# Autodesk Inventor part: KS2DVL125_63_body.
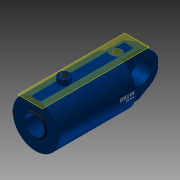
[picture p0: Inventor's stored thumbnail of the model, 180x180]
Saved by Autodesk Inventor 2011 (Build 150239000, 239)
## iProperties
Created: 2010-11
Document SubType Name: Modeling
Designer: TB
Mass: 405.061 g
Surface Area: 916.939 cm^2
Volume: 405.061 cm^3
Density: 1 g/cm^3
Author: TB
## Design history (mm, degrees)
sketch "Sketch2"
  geometry: L1 (-35, -3)-(-35, 3); L2 (-35, -9)-(-35, 9); L3 (-35, 0)-(-35, 72.5); L4 (-35, 72.5)-(-300, 72.5); L5 (-300, 72.5)-(-300, 72.5); L6 (-300, 72.5)-(-310, 72.5); L7 (-310, 72.5)-(-310, 35.5); L8 (-310, 35.5)-(-313, 32.5); L9 (-313, 32.5)-(-313, 31.5); L10 (-313, 31.5)-(-218, 31.5); L11 (-218, 31.5)-(-218, 62.5); L12 (-218, 62.5)-(-66, 62.5); L13 (-66, 62.5)-(-66, 0); L14 (-66, 0)-(-35, 0); L15 (-66, 0)-(-148.421, 0); L16 (-35, 9)-(-32, 12) reference; L17 (-32, 12)-(-35, 12) reference; L18 (-35, 12)-(-35, 9) reference; L19 (-32, 12)-(-35, 9) reference; L20 (-32, 12)-(-35, 12) reference; L21 (-35, 9)-(-35, 12) reference; L22 (-35, 9)-(-32, 12) reference; 1 further point
  constraints: 44 end point, 8 perpendicular, 6 parallel, 5 collinear, 2 horizontal, 2 vertical, 1 coincident, 1 midpoint, 1 point on line, 10 other
  dimensions: "DiaY" = 145 diameter of L4 L15; "DiaI" = 125 diameter of L12 L15; "d4" = 1 distance of L8.end L9.end; "d5" = 45 deg angle of L10 L8; "d6" = 3 distance between parallel lines of L7 L9; "DiaStang" = 63 diameter of L10 L15; "RindDia" = 145 diameter of L6 L15; "RingLengde" = 10 distance of L5.end L6.end; "RingTykk" = 92 distance between parallel lines of L11 L7; "KroppLengde" = 275 distance between parallel lines of L7 L3 (derived); "BunnTykkelse" = 31 distance between parallel lines of L13 L3
revolve "Kropp" sketch "Sketch2" stored, may be unused: angle "d13" = 90 deg
sketch "Sketch3"
  geometry: L1 (-66, -62.5)-(-66, 62.5) reference; L2 (-66, 0.01)-(-166, 0.01); L3 (-166, -0.01)-(-66, -0.01); A1 r 0.01 centre (-166, 0) between (-166, 0.01) and (-166, -0.01); A2 r 0.01 centre (-66, 0) between (-66, -0.01) and (-66, 0.01); 2 further points
  constraints: 4 end point, 4 point on circle, 4 tangent, 2 centre point, 1 coincident, 1 midpoint, 1 parallel, 1 perpendicular
  dimensions: "d17" = 0.01 radius of A2; "d18" = 100 distance of L2.start L2.end (= Slaglengde)
feature "BaneTransitionalConstraint" sketch "Sketch3" dims "d19" = 2, "d20" = 0
sketch "Sketch6"
  geometry: L1 (-101.5, 0)-(101.5, 0) reference; L2 (14.671, 71)-(-11.843, 71); L3 (72.5, 0)-(72.5, 31.248); L4 (-72.5, 0)-(-72.5, -18.451); A1 r 72.5 centre (0, 0) between (-72.5, 0) and (72.5, 0) reference; 2 further points
  constraints: 6 end point, 2 point on circle, 2 vertical, 2 other
  dimensions: "d30" = 71 distance from line of point (0, 0) L2 (computed from DiaY); "d31" = 0 deg angle of L1 L2 (computed from Vinkel_Plussport); "d37" = 90 deg angle of L2 L3; "d38" = 90 deg angle of L2 L4
  node "Projected Loop3"
workplane "Work Plane5"
sketch "Sketch7"
  geometry: L1 (14.671, -375.6)-(14.671, 62.6) reference; L2 (-19.633, -35)-(38.367, -35) reference; C1 r 17.5 at (14.671, -52.5); 1 further point
  constraints: 1 centre point, 1 point on line
  dimensions: "PortDia" = 35 diameter of C1
extrude "Extrusion2" cut sketch "Sketch7" stored distance "d34" = 1.5; taper "d35" = 0 deg
workplane "Work Plane7"
sketch "Sketch4"
  geometry: L1 (-16.68, -40)-(-16.68, -78.777); L2 (-16.68, -78.777)-(16.68, -78.777); L3 (16.68, -78.777)-(16.68, -40); L4 (16.68, -40)-(-16.68, -40); L5 (-40.643, -40)-(0, -40); L6 (-29, -35)-(29, -35); L7 (0, -35)-(0, -40); 2 further points
  constraints: 6 end point, 2 midpoint, 2 other
  dimensions: "d40" = 5 distance of L7.start L5.end
emboss "Emboss1" sketch "Sketch4" dims "d4" = 1, "d5" = 45 deg, "d6" = 3, "d22" = 0.2, "d23" = 0, "DiaI" = 125, "DiaY" = 145, "RindDia" = 145, "DiaStang" = 63, "RingTykk" = 92, "RingLengde" = 10, "KroppLengde" = 275 (derived), "BunnTykkelse" = 31
workplane "Work Plane8"
sketch "Sketch8"
  geometry: L1 (-29, -35)-(29, -35); L2 (0, -35)-(0, -40); L3 (-5.906, -110.587)-(-5.906, -40); L4 (-5.906, -40)-(5.906, -40); L5 (5.906, -40)-(5.906, -110.587); L6 (5.906, -110.587)-(-5.906, -110.587); L7 (72.5, -35)-(-72.5, -35); L8 (72.5, -35)-(-72.5, -35) reference; 3 further points
  constraints: 6 end point, 4 midpoint, 2 other
  dimensions: "d42" = 5 distance of L2.start L2.end
emboss "Emboss2" sketch "Sketch8" dims "d4" = 1, "d5" = 45 deg, "d6" = 3, "d43" = 0.2, "d44" = 0, "DiaI" = 125, "DiaY" = 145, "RindDia" = 145, "DiaStang" = 63, "RingTykk" = 92, "RingLengde" = 10, "KroppLengde" = 275 (derived), "BunnTykkelse" = 31
sketch "Sketch9"
  geometry: A1 r 12.5 centre (9.367, -52.5) between (0, -60.776) and (18.735, -60.776) reference; 1 further point
hole "Hole1" sketch "Sketch9" at (9.367, -52.5) diameter "d45" = 14.95; stored, may be unused: countersink angle "d49" = 82 deg, drill point angle "d51" = 118 deg; dims "d46" = 6, "d47" = 3.023, "d48" = 2, "DiaInvPluss" = 24.5
workplane "Work Plane9"
sketch "Sketch10"
  geometry: L1 (-101.5, 0)-(101.5, 0) reference; L2 (0, 72.5)-(13.136, 72.5); L3 (0, 72.5)-(0, 31.79); L4 (17.5, 70.356)-(17.5, 90); L5 (17.5, 90)-(0, 90); L6 (0, 90)-(0, 72.5); L7 (0, 72.5)-(17.5, 70.356); C1 r 72.5 at (0, 0) reference; A1 r 72.5 centre (0, 0) between (0, 72.5) and (17.5, 70.356); 1 further point
  constraints: 12 end point, 4 perpendicular, 2 concentric, 2 point on circle, 1 centre point, 1 point on line, 1 tangent
  dimensions: "d53" = 0 deg angle of L1 L2 (computed from Vinkel_Minusport); "DiaUtvStussMinus" = 35 diameter of L4 L3; "HøydeStussMinuss" = 17.5 distance between parallel lines of L2 L5
revolve "Revolution2" sketch "Sketch10" stored, may be unused: angle "d56" = 90 deg
hole "Hole2" diameter "d59" = 24.117; stored, may be unused: countersink angle "d63" = 82 deg, drill point angle "d65" = 118 deg; dims "d57" = 10, "d58" = 10, "d60" = 6, "d61" = 3.023, "d62" = 2, "DiaInvStussMinus" = 24.5
fillet "Fillet1" dims "d66" = 2
sketch "Sketch15"
  geometry: L1 (25, -68.053)-(25, 68.053); L2 (-25, -68.053)-(-25, 68.053); L3 (0, 101.5)-(0, -101.5) reference; A1 r 72.5 centre (0, 0) between (25, -68.053) and (-25, -68.053) reference; A2 r 72.5 centre (0, 0) between (25, 68.053) and (-25, 68.053); A3 r 72.5 centre (0, 0) between (-25, -68.053) and (25, -68.053)
  constraints: 8 point on circle, 4 end point, 4 point on line, 2 centre point, 2 concentric, 2 parallel, 1 coincident
  dimensions: "EyeBunnTykk" = 25 distance from line of L1 A1.centre; "EyeBunnTykk2" = 25 distance from line of A1.centre L2
extrude "Extrusion6" join sketch "Sketch15" taper "d98" = 0 deg; distance "LengdeEyeMinussBunntykk" = 136
sketch "Sketch16"
  geometry: L1 (-309, 72.5)-(101, 72.5) reference; L2 (-309, -72.5)-(101, -72.5) reference; L3 (-309, 72.5)-(101, 72.5) reference; L4 (101, 72.5)-(101, 68.053) reference; L5 (101, -68.053)-(101, 68.053) reference; L6 (-355.272, 0)-(192.63, 0) reference; L7 (36.5, 72.5)-(101, 72.5); L8 (101, 72.5)-(101, 8); A1 r 64.5 centre (36.5, 8) between (101, 8) and (36.5, 72.5); 6 further points; 2 other entities
  constraints: 4 end point, 4 tangent, 2 point on circle, 2 point on line, 1 centre point, 1 collinear, 1 perpendicular, 2 other
  dimensions: "d137" = 8 distance from line of L8.end L6
extrude "Extrusion7" cut sketch "Sketch16" taper "d102" = 0 deg; stored distance "ExtruEyeBunn" = 50
mirror "Mirror1"
sketch "Sketch20"
  geometry: L1 (-309, 72.5)-(101, 72.5) reference; L2 (101, -68.053)-(101, 68.053) reference; L3 (101, 72.5)-(101, 68.053) reference; L4 (-353.49, 0)-(181.938, 0) reference; L5 (-35, -68.053)-(-35, 68.053) reference; L6 (-35, 0)-(36, 0); L7 (36, 0)-(36, 20.918); L8 (69.354, 57.771)-(50.804, 68.481); A1 r 66.708 centre (36, 0) between (101, 15) and (69.354, 57.771); A2 r 35 centre (43.843, 37.5) between (43.843, 72.5) and (43.843, 72.5); A3 r 30 centre (35.804, 42.5) between (50.804, 68.481) and (35.804, 72.5); 1 further point
  constraints: 6 end point, 6 point on circle, 5 point on line, 4 tangent, 3 centre point, 1 coincident, 1 midpoint, 1 perpendicular
  dimensions: "d147" = 71 distance of L6.start L6.end; "d157" = 15 distance from line of L4 A1.start; "d158" = 30 deg angle of L1 L8; "d160" = 30 radius of A3
extrude "Extrusion10" cut sketch "Sketch20" stored distance "d144" = 10; taper "d145" = 0 deg
mirror "Mirror2"
sketch "Sketch17"
  geometry: L1 (136.107, 0)-(0, 0) reference; L2 (68.053, -360.8)-(68.053, 218.8) reference; C1 r 40 at (68.053, 71); 1 further point
  constraints: 1 centre point, 1 point on line
  dimensions: "DiaHullEyeBunn" = 80 diameter of C1; "d125" = 71 distance from line of C1.centre L1
extrude "Extrusion8" cut sketch "Sketch17" taper "d105" = 0 deg; distance "ExtruHullEye" = 50
pattern_circular "Circular Pattern1 Only Subsea" dims "d108" = 180 deg (derived)
workplane "Work Plane11"
sketch "Sketch18"
  geometry: L1 (0, -79.2)-(0, 13.2) reference; L2 (62.5, -66)-(-62.5, -66) reference; L3 (62.5, -66)-(-62.5, -66) reference; C1 r 17.5 at (0, -29); 1 further point
  constraints: 1 centre point
  dimensions: "DiaForsenkPlussPort" = 35 diameter of C1; "PlassPlussport" = 37 distance from line of L2 C1.centre
extrude "Extrusion9" cut sketch "Sketch18" stored distance "d113" = 10; taper "d114" = 0 deg
sketch "Sketch19"
  geometry: 10 further points
  constraints: 1 other
hole "Hole3" sketch "Sketch19" at (0, -29) diameter "d115" = 24.117; stored, may be unused: countersink angle "d119" = 90 deg, drill point angle "d121" = 118 deg; dims "d116" = 6, "d117" = 4, "d118" = 2, "d120" = 14.5
pattern_circular "Circular Pattern2 Only Subsea" dims angle "d123" = 360 deg
body "Solid1"
chamfer "Chamfer" distance "Chamfer" = 1; stored, may be unused: second distance "d15" = 2, angle "d16" = 45 deg
node "Projected Loop2"
body "Srf1"
node "Projected Loop10"
other parameters: "Slaglengde" = 100, "Forlengelse_rør" = 0, "Vinkel_Plussport" = 0 [user parameter; used in 1 equation term], "Vinkel_Minusport" = 0, "d32" = 90 deg, "d39" = 90 deg, "d41" = 90 deg, "Minusport2" = 180 deg, "ForsenkningPlussPort" = 70.7 (derived), "EyeLengdeUBunn" = 136
